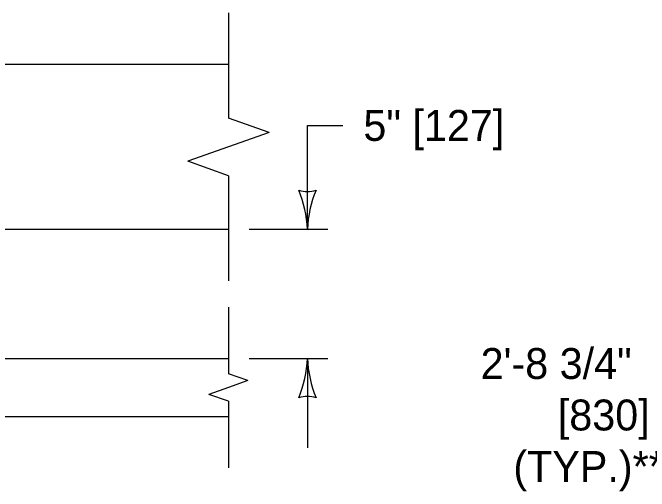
# Model space of a CAD drawing. Extents: x 49991.4 to 50021, y 49987.6 to 50011.4.
# Drawn here: x 50003.755 to 50004.991, y 49993.181 to 49994.11 of the extents above; entities that cross this region are included whole.
import ezdxf

# ---------------------------------------------------------------- set-up
doc = ezdxf.new("R2010")
doc.units = 0
for name, color, linetype in [('Level 1', 7, 'Continuous'), ('Level 2', 7, 'Continuous'), ('Level 3', 7, 'Continuous'), ('Level 6', 7, 'Continuous')]:
    doc.layers.add(name, color=color, linetype=linetype)

msp = doc.modelspace()

# ---------------------------------------------------------------- linework, layer by layer
at = {"layer": 'Level 1'}
for p, q in [((50002.717, 49994.0102), (50003.7869, 49994.0102)), ((50003.7869, 49994.0102), (50004.1738, 49994.0102)), ((50003.7104, 49993.6897), (50004.1738, 49993.6897)), ((50003.4526, 49993.4387), (50004.1738, 49993.4387)), ((50003.4526, 49993.3264), (50004.1738, 49993.3264))]:
    msp.add_line(p, q, dxfattribs=at)
at = {"layer": 'Level 3'}
for p, q in [((50004.3271, 49993.6897), (50004.3271, 49993.8914)), ((50004.3271, 49993.8914), (50004.3959, 49993.8914)), ((50004.2138, 49993.6897), (50004.3671, 49993.6897)), ((50004.2138, 49993.4387), (50004.3671, 49993.4387)), ((50004.3271, 49993.4387), (50004.3271, 49993.2653))]:
    msp.add_line(p, q, dxfattribs=at)
for centre, radius, start, end in [((50004.3271, 49993.8179), 0.0548, 252.1388, 287.8612), ((50004.0944, 49993.6782), 0.233, 2.8273, 22.0772), ((50004.5492, 49993.6805), 0.2223, 157.456, 177.6395), ((50004.1049, 49993.4479), 0.2223, 337.456, 357.6395), ((50004.5598, 49993.4502), 0.233, 182.8273, 202.0772), ((50004.3271, 49993.3105), 0.0548, 72.1388, 107.8612)]:
    msp.add_arc(centre, radius, start, end, dxfattribs=at)
at = {"layer": 'Level 6'}
for p, q in [((50004.1738, 49994.1102), (50004.1738, 49993.9057)), ((50004.2529, 49993.8777), (50004.1738, 49993.9057)), ((50004.2529, 49993.8777), (50004.1738, 49993.85)), ((50004.1738, 49993.85), (50004.0948, 49993.8217)), ((50004.1738, 49993.7938), (50004.0948, 49993.8217)), ((50004.1738, 49993.7938), (50004.1738, 49993.5897)), ((50004.1738, 49993.5387), (50004.1738, 49993.4093)), ((50004.2117, 49993.396), (50004.1738, 49993.4093)), ((50004.2117, 49993.396), (50004.1738, 49993.3825)), ((50004.1738, 49993.3825), (50004.1359, 49993.369)), ((50004.1738, 49993.3557), (50004.1359, 49993.369)), ((50004.1738, 49993.3557), (50004.1738, 49993.2264))]:
    msp.add_line(p, q, dxfattribs=at)

# ---------------------------------------------------------------- texts
at = {"layer": 'Level 2'}
for s, p in [('5" [127]', (50004.4359, 49993.8614)), ('2\'-8 3/4"', (50004.6637, 49993.3991)), ('[830]', (50004.8137, 49993.2991)), ('(TYP.)**', (50004.7273, 49993.1991))]:
    msp.add_text(s, height=0.06, dxfattribs=at).set_placement(p)

doc.saveas('drawing.dxf')
